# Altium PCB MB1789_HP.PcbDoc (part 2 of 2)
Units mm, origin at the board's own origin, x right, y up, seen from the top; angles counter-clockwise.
Board outline 60 x 34 mm, 4 copper layers (Top Layer, Mid-Layer 1, Mid-Layer 2, Bottom Layer), stack 1.07 mm thick; 66 components, 56 nets, 212 pads, 990 vias.
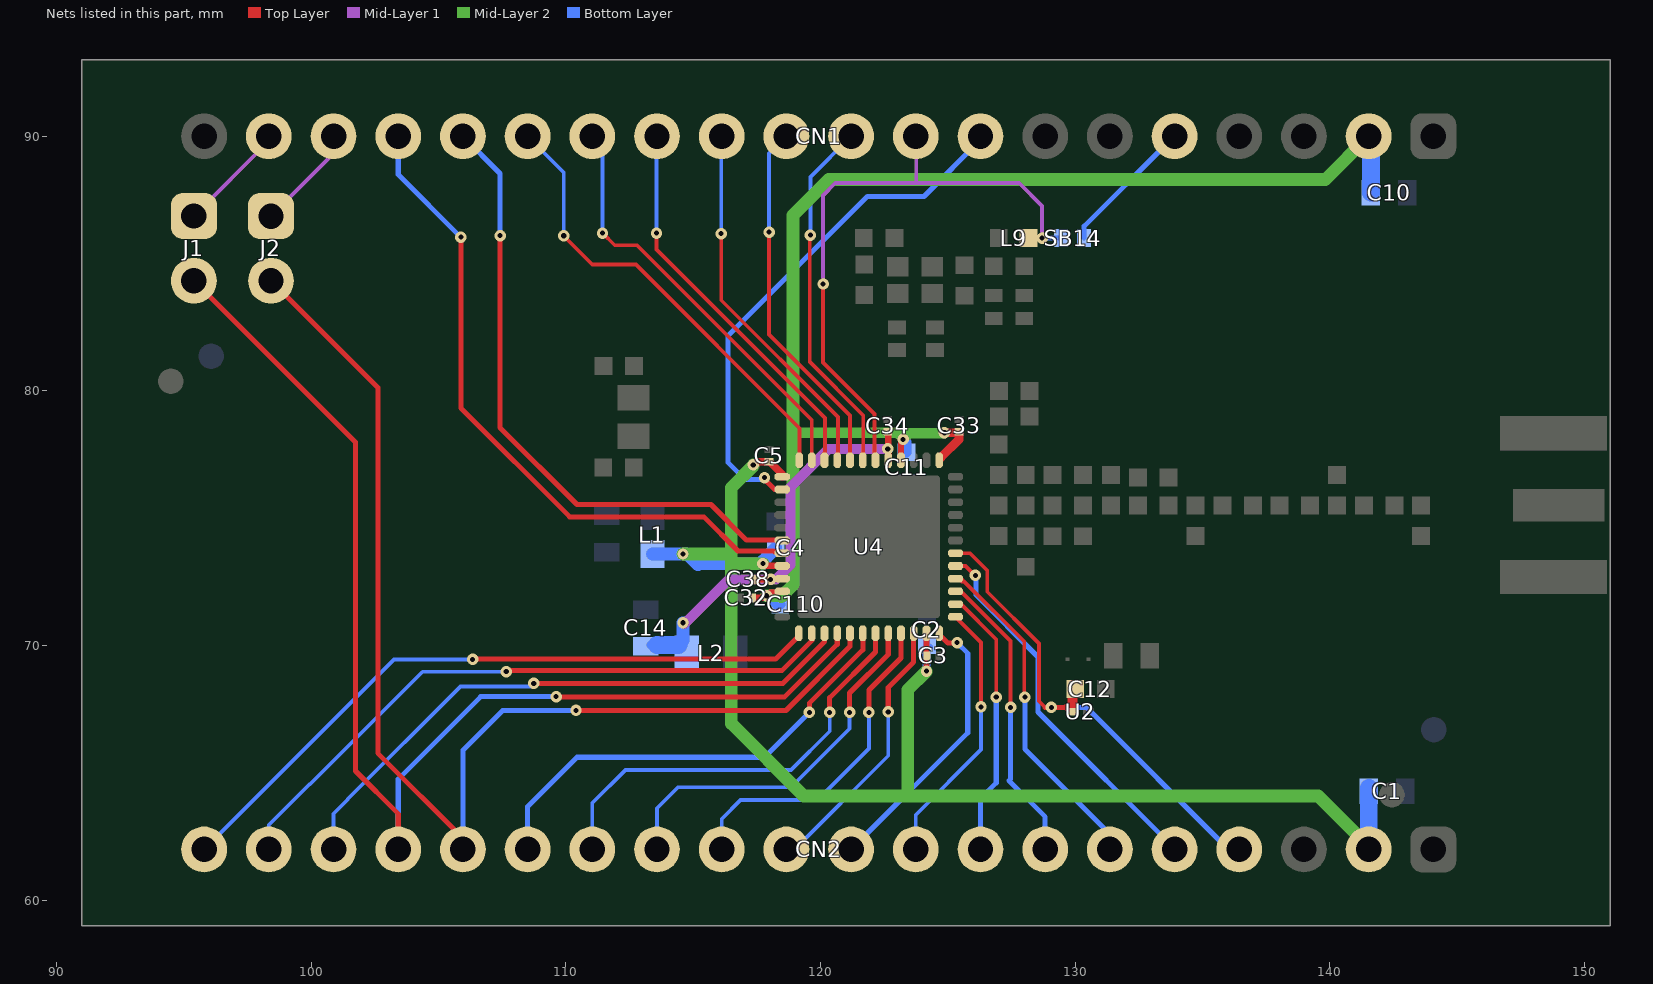
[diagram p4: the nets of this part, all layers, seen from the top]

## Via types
v1: diameter 0.45, hole 0.2, Top Layer to Bottom Layer, 990 vias

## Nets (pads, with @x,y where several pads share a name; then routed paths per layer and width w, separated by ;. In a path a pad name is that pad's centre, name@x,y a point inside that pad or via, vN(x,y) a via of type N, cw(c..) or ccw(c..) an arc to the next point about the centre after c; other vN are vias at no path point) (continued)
NRST: C12.1 CN2.4 U2.1 U4.18 | length 19.4
  Top Layer w0.15: U4.18@125.296,73.632 125.865,73.632 126.545,72.952 126.545,72.121 128.58,70.085 128.58,67.82 128.82,67.58
  Top Layer w0.2: 128.82,67.58 v1(129.06,67.58) 129.588,67.58 129.608,67.6 129.648,67.56 129.688,67.6 U2.1@129.788,67.5 ; C12.1@129.888,68.188 C12.1@130,68.3
  Top Layer w0.4: U2.1@129.888,67.5 C12.1@129.888,68.188
  Bottom Layer w0.2: v1(129.06,67.58) 130.44,67.58 136.02,62 CN2.4@136.44,62
PA0: CN2.14 U4.7 | length 16.9
  Top Layer w0.2: v1(120.36,67.38) 120.36,67.957 122.158,69.755 U4.7@122.158,70.485
  Bottom Layer w0.15: CN2.14@111.04,62 111.04,63.82 112.34,65.12 118.84,65.12 120.36,66.64 v1(120.36,67.38)
PA1: CN2.13 U4.8 | length 14.8
  Top Layer w0.2: v1(121.14,67.38) 121.14,68.14 122.658,69.658 U4.8@122.658,70.485
  Bottom Layer w0.15: CN2.13@113.58,62 113.58,63.62 114.4,64.44 118.84,64.44 121.14,66.74 v1(121.14,67.38)
PA2: CN2.12 U4.9 | length 13.2
  Top Layer w0.2: v1(121.9,67.38) 121.9,68.26 123.158,69.518 U4.9@123.158,70.485
  Bottom Layer w0.15: CN2.12@116.12,62 116.12,63.2 116.86,63.94 119.88,63.94 121.9,65.96 v1(121.9,67.38)
PA3: CN2.11 U4.10 | length 10.8
  Top Layer w0.2: v1@122.6,67.36 122.66,67.42 122.66,68.36 123.658,69.358 U4.10@123.658,70.485
  Bottom Layer w0.15: CN2.11@118.66,62 118.98,62 122.66,65.68 v1(122.66,67.4)
PA4: CN2.10 U4.12 | length 11.1
  Top Layer w0.2: U4.12@124.658,70.485 124.658,70.442 125,70.1 v1@125.4,70.1
  Bottom Layer w0.2: CN2.10@121.2,62 125.78,66.58 125.78,69.7 v1(125.36,70.12)
PA5: CN2.9 U4.13 | length 10.6
  Top Layer w0.15: U4.13@125.296,71.132 126.3,70.128 v1(126.3,67.6)
  Bottom Layer w0.15: CN2.9@123.74,62 123.74,63.36 126.3,65.92 v1(126.3,67.6)
PA6: CN2.8 U4.14 | length 10.7
  Top Layer w0.15: U4.14@125.296,71.632 125.51,71.632 126.9,70.242 v1(126.9,67.98)
  Bottom Layer w0.2: CN2.8@126.28,62 126.28,64 126.9,64.62 v1(126.9,67.98)
PA7: CN2.7 U4.15 | length 11.8
  Top Layer w0.15: U4.15@125.296,72.132 125.51,72.132 127.46,70.182 v1(127.46,67.58)
  Bottom Layer w0.2: v1(127.46,67.58) 127.46,64.76 127.4,64.7 128.82,63.28 CN2.7@128.82,62
PA8: CN2.6 U4.16 | length 13.3
  Top Layer w0.15: U4.16@125.296,72.632 125.528,72.632 125.555,72.605 125.555,72.522 125.638,72.522 128,70.16 v1@128,68
  Bottom Layer w0.2: v1(128.02,67.98) 128.02,65.94 131.36,62.6 CN2.6@131.36,62
PA9: CN2.5 U4.17 | length 15.1
  Top Layer w0.15: U4.17@125.296,73.132 125.688,73.132 v1@126.08,72.74 ; v1@126.08,72.74 v1(126.08,72.76)
  Bottom Layer w0.2: v1@125.99,72.76 126.1,72.76 126.1,72 128.54,69.56 128.54,67.4 CN2.5@133.95,61.99
PA10: CN1.12 U4.33 | length 14.9
  Top Layer w0.15: v1@116.1,86.22 v1(116.1,86.18) 116.1,83.56 120.68,78.98 U4.33@120.68,77.26 ; U4.33@120.658,77.282 U4.33@120.658,77.541
  Bottom Layer w0.15: v1(116.1,86.18) 116.1,89.98 CN1.12@116.12,90
PA11: CN1.13 U4.34 | length 15.9
  Top Layer w0.15: v1@113.56,86.26 v1(113.56,86.2) 113.56,85.56 120.18,78.94 U4.34@120.18,77.3 ; U4.34@120.14,77.2 U4.34@120.14,77.54
  Bottom Layer w0.15: v1(113.56,86.2) 113.56,89.98 CN1.13@113.58,90
PA12: CN1.14 U4.35 | length 16.8
  Top Layer w0.15: v1(111.44,86.2) 111.92,85.72 112.8,85.72 119.658,78.862 U4.35@119.658,77.282
  Bottom Layer w0.15: CN1.14@111.04,90 111.44,89.6 v1(111.44,86.2)
PA13: CN1.15 U4.36 | length 18.8
  Top Layer w0.15: v1@109.92,86.08 111.04,84.96 112.76,84.96 119.18,78.54 U4.36@119.18,77.3
  Mid-Layer 1 w0.15: CN1.15@108.5,89.32 CN1.15@108.5,90
  Bottom Layer w0.15: CN1.15@108.5,90 109.92,88.58 v1(109.92,86.095)
PA14: CN1.16 U4.42 | length 24.9
  Top Layer w0.2: v1@107.42,85.92 107.42,78.56 110.44,75.54 115.7,75.54 117.098,74.142 U4.42@118.62,74.142
  Bottom Layer w0.2: CN1.16@105.96,90 107.42,88.54 v1(107.42,86.1)
PA15: CN1.17 U4.43 | length 26.8
  Top Layer w0.2: v1(105.88,86.04) 105.88,79.331 110.151,75.06 115.42,75.06 116.76,73.72 118.16,73.72 118.2,73.68 118.523,73.68 U4.43@118.58,73.622
  Bottom Layer w0.2: CN1.17@103.42,90 103.42,88.5 v1(105.88,86.04)
PB0: CN1.9 L9.2 SB14.1 U4.30 | length 25
  Top Layer w0.15: v1(120.1,84.2) 120.1,84.18 120.16,84.12 120.08,84.04 120.1,84.02 120.1,81.12 122.125,79.095 122.125,77.315 U4.30@122.158,77.282
  Top Layer w0.2: L9.2@128.16,86 v1(128.7,86)
  Mid-Layer 1 w0.15: v1@120.1,84.08 120.1,87.68 120.58,88.16 127.8,88.16 128.7,87.26 v1(128.7,86) ; CN1.9@123.74,89.94 123.76,89.96 123.76,88.16
  Bottom Layer w0.2: v1(128.7,86) SB14.1@129.45,86
PB2: CN1.10 U4.31 | length 14.7
  Top Layer w0.15: v1(119.6,86.12) 119.66,86.12 119.58,86.2 119.58,81.14 121.68,79.04 U4.31@121.68,77.32 ; U4.31@121.658,77.282 U4.31@121.658,77.562
  Bottom Layer w0.15: v1(119.6,86.12) 119.6,88.4 CN1.10@121.2,90
PB3: CN2.20 U4.1 | length 26.9
  Top Layer w0.2: v1@106.36,69.48 118.24,69.48 119.151,70.391 U4.1@119.151,70.485
  Bottom Layer w0.15: CN2.20@95.8,62 103.26,69.46 v1(106.34,69.46)
PB4: CN2.19 U4.2 | length 25.5
  Top Layer w0.2: v1@107.66,69.02 118.48,69.02 119.658,70.198 U4.2@119.658,70.485
  Bottom Layer w0.15: CN2.19@98.34,62 98.34,62.96 99.94,64.56 99.96,64.56 104.38,68.98 v1(107.66,68.98)
PB5: CN2.18 U4.3 | length 23.8
  Top Layer w0.2: v1@108.78,68.52 118.52,68.52 120.158,70.158 U4.3@120.158,70.485
  Bottom Layer w0.15: CN2.18@100.88,62 100.88,63.4 101.44,63.96 101.44,63.98 105.86,68.4 108.62,68.4 v1(108.74,68.52)
PB6: CN2.17 J1.2 U4.4 | length 48.3
  Top Layer w0.2: J1.2@95.4,84.33 101.74,77.99 101.74,65.08 103.42,63.4 CN2.17@103.42,62 ; v1@109.58,67.98 118.58,67.98 120.658,70.058 U4.4@120.658,70.485
  Bottom Layer w0.2: CN2.17@103.42,62 103.42,64.76 106.66,68 v1(109.62,68)
PB7: CN2.16 J2.2 U4.5 | length 46.7
  Top Layer w0.2: J2.2@98.425,84.328 102.62,80.133 102.62,65.78 105.96,62.44 CN2.16@105.96,62 ; v1(110.4,67.46) 118.64,67.46 121.158,69.978 U4.5@121.158,70.485
  Bottom Layer w0.2: CN2.16@105.96,62 105.96,65.9 107.52,67.46 v1(110.4,67.46)
PB8: CN2.15 U4.6 | length 18.7
  Top Layer w0.15: U4.6@121.618,70.445 U4.6@121.658,70.485 U4.6@121.658,70.235
  Top Layer w0.2: v1@119.56,67.34 v1(119.56,67.38) 119.56,67.74 121.66,69.84 U4.6@121.66,70.56
  Bottom Layer w0.2: CN2.15@108.5,62 108.5,63.68 110.44,65.62 117.8,65.62 v1(119.56,67.38)
PB12: CN1.11 U4.32 | length 14.3
  Top Layer w0.15: v1@117.98,86.26 117.98,82.22 121.158,79.042 U4.32@121.158,77.282
  Bottom Layer w0.15: v1(117.98,86.24) 117.98,89.32 CN1.11@118.66,90
PC13: CN1.8 U4.38 | length 21.1
  Top Layer w0.2: v1(117.8,76.6) 117.869,76.6 117.88,76.589 117.811,76.52 117.751,76.58 118.199,76.132 U4.38@118.498,76.132
  Bottom Layer w0.2: v1@117.811,76.52 117.04,76.52 116.36,77.2 116.36,82.161 121.839,87.64 124.06,87.64 CN1.8@126.32,89.9
UART_RX: CN1.18 J2.1 | length 4.1
  Mid-Layer 1 w0.15: J2.1@98.425,86.868 100.88,89.323 CN1.18@100.88,90
UART_TX: CN1.19 J1.1 | length 4.3
  Mid-Layer 1 w0.15: J1.1@95.4,86.87 98.34,89.81 CN1.19@98.34,90
VDD: C1.2 C2.2 C3.2 C4.2 C5.2 CN2.2 L1.1 U4.11 U4.37 U4.44 | length 58.8
  Top Layer w0.25: v1(117.74,73.22) 117.829,73.22 117.913,73.135 118.495,73.135 U4.44@118.498,73.132 ; v1@124.158,69.002 U4.11@124.158,70.485
  Top Layer w0.28: v1@117.32,77.06 117.48,77.22 C5.2@117.98,77.22 118.01,77.22 118.498,76.731 U4.37@118.498,76.632 ; v1@117.38,77.12 v1@117.44,77.12
  Mid-Layer 2 w0.3: 116.5,73.152 116.548,73.2
  Mid-Layer 2 w0.5: v1(114.6,73.6) 116.5,73.6 ; 116.548,73.2 116.573,73.175 116.658,73.26 116.698,73.22 v1(117.74,73.22) ; v1(117.36,77.1) 117.36,77.065 116.5,76.205 116.5,73.152 116.5,66.94 119.34,64.1 123.42,64.1 ; v1@124.15,68.99 123.42,68.26 123.42,64.1 ; CN2.2@141.56,62.08 139.54,64.1 123.42,64.1
  Bottom Layer w0.25: C2.2@124.18,70.02 C2.2@124.258,69.942
  Bottom Layer w0.3: v1(124.16,69) 124.16,69.844 C2.2@124.258,69.942
  Bottom Layer w0.5: L1.1@113.4,73.6 114.76,73.6 115.185,73.175 115.27,73.26 115.31,73.22 v1(117.74,73.22) 117.74,73.327 117.76,73.347 117.88,73.467 117.873,73.473 C4.2@118.24,73.84
  Bottom Layer w0.7: CN2.2@141.52,61.98 C1.2@141.52,64.42
VDD_TCXO_EXT: CN1.5 SB14.2 | length 5.1
  Bottom Layer w0.2: SB14.2@130.35,86 130.35,86.47 CN1.5@133.6,89.72
VDDPA: C10.1 C11.1 C32.2 C33.2 C110.1 CN1.2 U4.25 U4.28 U4.46 | length 53.3
  Top Layer w0.2: v1(117.88,71.96) 117.88,71.98 118.01,72.11 118.548,72.11 U4.46@118.6,72.162
  Top Layer w0.25: C32.2@117.4,71.88 117.8,71.88 v1(117.88,71.96) ; U4.28@123.158,77.282 123.158,78.038 123.22,78.1 v1(123.24,78.1) ; U4.25@124.658,77.282 U4.25@124.658,77.318
  Top Layer w0.35: U4.25@124.73,77.39 125.44,78.1 C33.2@125.44,78.36 ; v1(124.86,78.36) C33.2@125.425,78.36
  Mid-Layer 2 w0.4: 118.92,78.36 123.015,78.36 123.24,78.135 v1(123.24,78.1) 123.48,78.34 v1@124.84,78.34
  Mid-Layer 2 w0.5: v1(117.88,71.96) 118.42,71.96 118.46,71.92 118.92,72.38 ; 118.92,72.44 118.92,86.9 120.32,88.3 139.82,88.3 CN1.2@141.52,90
  Bottom Layer w0.4: v1(117.88,71.96) 117.94,71.96 117.98,71.92 118.28,71.62 C110.1@118.42,71.62 ; v1(123.24,78.1) 123.275,78.1 123.38,77.995 C11.1@123.38,77.598
  Bottom Layer w0.7: CN1.2@141.52,90 141.607,89.912 C10.1@141.607,87.78
VDDRF1V55: C14.1 C34.2 C38.1 L2.1 U4.29 U4.45 | length 17.3
  Top Layer w0.254: C38.1@117.42,72.6 117.44,72.62 117.46,72.6 v1(118.04,72.6) ; U4.29@122.658,77.282 C34.2@122.658,78.38
  Mid-Layer 1 w0.4: v1(114.6,70.9) 114.649,70.851 116.418,72.62 116.438,72.6 v1(118.04,72.6) 118.2,72.6 118.22,72.62 118.24,72.6 118.82,73.18 118.82,76.22 120.326,77.726 v1(122.64,77.726)
  Bottom Layer w0.4: C14.1@113.363,70.026 C14.1@113.574,70.026 ; L2.1@114.423,70.026 L2.1@114.6,70.204 ; L2.1@114.6,70.071 v1(114.6,70.9)
  Bottom Layer w0.5: L2.1@114.6,70.204 v1(114.6,70.9)
  Bottom Layer w0.7: C14.1@113.574,70.026 L2.1@114.423,70.026
pads on no net: CN1.3 CN1.7 CN2.3 Designator1.1 Designator2.1 Designator3.1 Designator4.1 Designator6.1 U4.22
copper on no net: | length 2656.1
  Top Layer w0.025: 179.628,186.047 182.16,188.579 185.208,191.627 188.256,194.675 191.304,197.723 194.352,200.771 197.4,203.819 200.448,206.867 203.496,209.915 206.544,212.963 208.068,214.487 ; 179.628,187.571 180.636,188.579 183.684,191.627 186.732,194.675 189.78,197.723 192.828,200.771 195.876,203.819 198.924,206.867 201.972,209.915 205.02,212.963 208.068,216.011 ; 179.628,189.095 182.16,191.627 185.208,194.675 188.256,197.723 191.304,200.771 194.352,203.819 197.4,206.867 200.448,209.915 203.496,212.963 206.544,216.011 208.068,217.535 ; 179.628,190.619 180.636,191.627 183.684,194.675 186.732,197.723 189.78,200.771 192.828,203.819 195.876,206.867 198.924,209.915 201.972,212.963 205.02,216.011 208.068,219.059 ; 179.628,192.143 182.16,194.675 185.208,197.723 188.256,200.771 191.304,203.819 194.352,206.867 197.4,209.915 200.448,212.963 203.496,216.011 206.544,219.059 ; 179.628,193.667 180.636,194.675 183.684,197.723 186.732,200.771 189.78,203.819 192.828,206.867 195.876,209.915 198.924,212.963 201.972,216.011 205.02,219.059 ; 179.628,195.191 182.16,197.723 185.208,200.771 188.256,203.819 191.304,206.867 194.352,209.915 197.4,212.963 200.448,216.011 203.496,219.059 ; 179.628,196.715 180.636,197.723 183.684,200.771 186.732,203.819 189.78,206.867 192.828,209.915 195.876,212.963 198.924,216.011 201.972,219.059 ; 179.628,198.239 182.16,200.771 185.208,203.819 188.256,206.867 191.304,209.915 194.352,212.963 197.4,216.011 200.448,219.059 ; 179.628,199.763 180.636,200.771 183.684,203.819 186.732,206.867 189.78,209.915 192.828,212.963 195.876,216.011 198.924,219.059 ; 179.628,201.287 182.16,203.819 185.208,206.867 188.256,209.915 191.304,212.963 194.352,216.011 197.4,219.059 ; 179.628,202.811 180.636,203.819 183.684,206.867 186.732,209.915 189.78,212.963 192.828,216.011 195.876,219.059 ; 179.628,204.335 182.16,206.867 185.208,209.915 188.256,212.963 191.304,216.011 194.352,219.059 ; 179.628,205.859 180.636,206.867 183.684,209.915 186.732,212.963 189.78,216.011 192.828,219.059 ; 179.628,207.383 182.16,209.915 185.208,212.963 188.256,216.011 191.304,219.059 ; 179.628,208.907 180.636,209.915 183.684,212.963 186.732,216.011 189.78,219.059 ; 179.628,210.431 182.16,212.963 185.208,216.011 188.256,219.059 ; 179.628,211.955 180.636,212.963 183.684,216.011 186.732,219.059 ; 179.628,213.479 182.16,216.011 185.208,219.059 ; 179.628,215.003 180.636,216.011 183.684,219.059 ; 179.628,216.527 182.16,219.059 ; 179.628,218.051 180.636,219.059 ; 180.636,185.531 183.684,188.579 186.732,191.627 189.78,194.675 192.828,197.723 195.876,200.771 198.924,203.819 201.972,206.867 205.02,209.915 208.068,212.963 ; 182.16,185.531 185.208,188.579 188.256,191.627 191.304,194.675 194.352,197.723 197.4,200.771 200.448,203.819 203.496,206.867 206.544,209.915 208.068,211.439 ; 183.684,185.531 186.732,188.579 189.78,191.627 192.828,194.675 195.876,197.723 198.924,200.771 201.972,203.819 205.02,206.867 208.068,209.915 ; 185.208,185.531 188.256,188.579 191.304,191.627 194.352,194.675 197.4,197.723 200.448,200.771 203.496,203.819 206.544,206.867 208.068,208.391 ; 186.732,185.531 189.78,188.579 192.828,191.627 195.876,194.675 198.924,197.723 201.972,200.771 205.02,203.819 208.068,206.867 ; 188.256,185.531 191.304,188.579 194.352,191.627 197.4,194.675 200.448,197.723 203.496,200.771 206.544,203.819 208.068,205.343 ; 189.78,185.531 192.828,188.579 195.876,191.627 198.924,194.675 201.972,197.723 205.02,200.771 208.068,203.819 ; 191.304,185.531 194.352,188.579 197.4,191.627 200.448,194.675 203.496,197.723 206.544,200.771 208.068,202.295 ; 192.828,185.531 195.876,188.579 198.924,191.627 201.972,194.675 205.02,197.723 208.068,200.771 ; 194.352,185.531 197.4,188.579 200.448,191.627 203.496,194.675 206.544,197.723 208.068,199.247 ; 195.876,185.531 198.924,188.579 201.972,191.627 205.02,194.675 208.068,197.723 ; 197.4,185.531 200.448,188.579 203.496,191.627 206.544,194.675 208.068,196.199 ; 198.924,185.531 201.972,188.579 205.02,191.627 208.068,194.675 ; 200.448,185.531 203.496,188.579 206.544,191.627 208.068,193.151 ; 201.972,185.531 205.02,188.579 208.068,191.627 ; 203.496,185.531 206.544,188.579 208.068,190.103 ; 205.02,185.531 208.068,188.579 ; 206.544,185.531 208.068,187.055
  Top Layer w0.381: 91.512,188.579 101.924,188.579 125.54,188.579 148.647,188.579 165.153,188.579 179.628,188.579 208.068,188.579 ; 91.512,191.627 101.924,191.627 125.54,191.627 148.647,191.627 165.153,191.627 179.628,191.627 208.068,191.627 ; 91.512,194.675 101.924,194.675 125.54,194.675 148.647,194.675 165.153,194.675 179.628,194.675 208.068,194.675 ; 91.512,197.723 101.924,197.723 125.54,197.723 148.647,197.723 165.153,197.723 179.628,197.723 208.068,197.723 ; 91.512,200.771 101.924,200.771 125.54,200.771 148.647,200.771 165.153,200.771 179.628,200.771 208.068,200.771 ; 91.512,203.819 101.924,203.819 125.54,203.819 148.647,203.819 165.153,203.819 179.628,203.819 208.068,203.819 ; 91.512,206.867 101.924,206.867 125.54,206.867 148.647,206.867 165.153,206.867 179.628,206.867 208.068,206.867 ; 91.512,209.915 101.924,209.915 125.54,209.915 148.647,209.915 165.153,209.915 179.628,209.915 208.068,209.915 ; 91.512,212.963 101.924,212.963 125.54,212.963 148.647,212.963 165.153,212.963 179.628,212.963 208.068,212.963 ; 91.512,216.011 101.924,216.011 125.54,216.011 148.647,216.011 165.153,216.011 179.628,216.011 208.068,216.011 ; 91.512,219.059 208.068,219.059 ; 101.924,222.107 101.924,185.531 ; 125.54,222.107 125.54,185.531 ; 148.647,222.107 148.647,185.531 ; 165.153,222.107 165.153,185.531 ; 179.628,222.107 179.628,185.531 ; 101.924,185.531 125.54,185.531 ; 101.924,185.531 91.512,185.531 91.512,222.107 208.068,222.107 208.068,185.531 179.628,185.531 ; 125.54,185.531 148.647,185.531 ; 148.647,185.531 165.153,185.531 ; 165.153,185.531 179.628,185.531

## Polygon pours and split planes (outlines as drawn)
GND on Top Layer "GND_Top" (solid, remove dead copper, pour order 0): 90.94,93.02 90.98,92.98 150.92,92.98 150.92,59.04 150.86,58.98 91.04,58.98 91.04,92.98
GND on Mid-Layer 1 "GND_L02_P002" (solid, remove dead copper, pour order 2): 91.04,92.98 150.96,92.98 150.96,59.08 151,59.04 150.94,58.98 91.04,58.98 91.04,92.98
GND on Mid-Layer 2 "GND_L03_P004" (solid, remove dead copper, pour order 4): 91.04,92.94 150.76,92.94 150.9,92.8 150.9,59.1 91.04,59.1 90.98,59.16 90.98,93
GND on Bottom Layer "GND_L04_P006" (solid, remove dead copper, pour order 6): 90.98,93 151.02,93 150.96,92.94 150.96,59.1 91.1,59.1 90.98,58.98 90.98,93

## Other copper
Top Layer:
  pour cut-out: 136.247,76.032 143.381,76.032 143.381,74.968 136.246,74.968
  region net NetC28_1: 146.214,75.819 147.139,76.155 147.195,76.155 147.195,74.885 147.167,74.885 146.214,75.218
  region net NetC27_2: 125.489,76.28 126.02,76.28 126.689,77 126.689,76.4 126.319,75.98 125.489,75.98
  pour cut-out: 125.6,77.4 127.54,77.4 127.54,71.5 125.6,73.44
  region net GND: 124.7,84.2 126.4,84.2 126.6,84 126.6,83.4 126.1,83.4 126.1,83 125.4,83 124.9,83.5 124.7,83.5
  pour cut-out: 127.4,80.462 127.7,80.462 127.7,77.2 127.4,77.2
  pour cut-out: 111.84,79.2 113.3,79.2 113.3,78.7 111.84,78.7
  pour cut-out: 111.9,77.4 112.3,77.4 112.3,76.6 112.2,76.7 111.9,76.7
  pour cut-out: 111.9,81.54 112.3,81.54 112.3,80.74 112,80.74 111.9,80.84
  pour cut-out: 127.2,85.3 127.7,85.3 127.7,84.6 127.6,84.5 127.2,84.5
  pour cut-out: 127.4,86.4 127.8,86.4 127.8,85.6 127.4,85.6
  pour cut-out: 122.1,86.4 122.6,86.4 122.6,85.5 122.5,85.6 122.1,85.6
  pour cut-out: 130.462,68.762 130.525,68.7 130.9,68.7 130.9,67.9 130.4,67.9
  pour cut-out: 127.424,73.986 127.49,73.92 129.95,73.92 129.95,73.42 128.29,73.42 127.521,73.42 127.424,73.518
  pour cut-out: 132.925,77.132 133.198,77.132 133.196,74.968 132.923,74.968
  pour cut-out: 126.7,75.1 130.7,75.1 130.7,74.7 126.7,74.7
  pour cut-out: 126.7,76.3 129.941,76.3 129.941,75.972 126.705,75.972 126.695,75.961
  pour cut-out: 129.565,77.215 129.838,77.215 129.838,73.838 129.565,73.838
  pour cut-out: 123.4,77.5 123.4,79.6 121.4,81.6 120.96,82.04 120.96,84.8 121.9,84.8 121.9,86.5 128.8,86.5 128.8,84.8 128.8,81.8 128.8,82 128.3,81.4 126.04,81.4 124.6,79.96 124.6,77.8 124.3,77.5
  region net NetC15_1: 125.1,76.7 125.1,77 126.3,78.2 127,78.2 127,77.6 126.4,77.6 125.5,76.7
  pour cut-out: 118.72,77.04 125.04,77.04 124.98,76.98 124.98,70.76 119.02,70.76 118.82,70.76 119.34,71.28 119.34,71.6 119.2,71.74 118.721,71.261
  pour cut-out: 125.16,78.82 125.72,78.82 125.72,78.46 125.7,78.44 125.16,78.44 125.16,78.78 125.18,78.8
  pour cut-out: 122.38,78.8 122.94,78.8 122.94,78.44 122.92,78.42 122.38,78.42 122.38,78.76 122.4,78.78
  pour cut-out: 117.68,77.64 118.24,77.64 118.24,77.28 118.22,77.26 117.68,77.26 117.68,77.6 117.7,77.62
  pour cut-out: 116.94,72.36 116.94,72.92 117.3,72.92 117.32,72.9 117.32,72.36 116.98,72.36 116.96,72.38
  pour cut-out: 116.88,71.54 116.88,72.1 117.24,72.1 117.26,72.08 117.26,71.54 116.92,71.54 116.9,71.56
  pour cut-out: 124.54,69.84 124.54,69.28 124.18,69.28 124.16,69.3 124.16,69.84 124.5,69.84 124.52,69.82
  text "Layer" at 93.29,219.821 h1.52
  text "Name" at 103.702,219.821 h1.52
  text "Material" at 127.318,219.821 h1.52
  text "Thickness" at 150.425,219.821 h1.52
  text "Constant" at 166.931,219.821 h1.52
  text "Board Layer Stack" at 181.406,219.821 h1.52
  text "Top Overlay" at 103.702,216.773 h1.52
  text "Top Solder" at 103.702,213.725 h1.52
  text "Solder Resist" at 127.318,213.725 h1.52
  text "0.79mil" at 150.425,213.725 h1.52
  text "3.7" at 166.931,213.725 h1.52
  text "1" at 93.29,210.677 h1.52
  text "Top Layer" at 103.702,210.677 h1.52
  text "Copper" at 127.318,210.677 h1.52
  text "1.38mil" at 150.425,210.677 h1.52
  text "Dielectric 1" at 103.702,207.629 h1.52
  text "1x106 + 1x2116" at 127.318,207.629 h1.52
  text "6.30mil" at 150.425,207.629 h1.52
  text "3.7" at 166.931,207.629 h1.52
  text "2" at 93.29,204.581 h1.52
  text "Mid-Layer 1" at 103.702,204.581 h1.52
  text "Copper" at 127.318,204.581 h1.52
  text "1.38mil" at 150.425,204.581 h1.52
  text "Dielectric2" at 103.702,201.533 h1.52
  text "FR-4" at 127.318,201.533 h1.52
  text "24.02mil" at 150.425,201.533 h1.52
  text "5" at 166.931,201.533 h1.52
  text "3" at 93.29,198.485 h1.52
  text "Mid-Layer 2" at 103.702,198.485 h1.52
  text "Copper" at 127.318,198.485 h1.52
  text "1.38mil" at 150.425,198.485 h1.52
  text "Dielectric3" at 103.702,195.437 h1.52
  text "1x106 + 1x2116" at 127.318,195.437 h1.52
  text "6.30mil" at 150.425,195.437 h1.52
  text "3.7" at 166.931,195.437 h1.52
  text "4" at 93.29,192.389 h1.52
  text "Bottom Layer" at 103.702,192.389 h1.52
  text "Copper" at 127.318,192.389 h1.52
  text "1.38mil" at 150.425,192.389 h1.52
  text "Bottom Solder" at 103.702,189.341 h1.52
  text "Solder Resist" at 127.318,189.341 h1.52
  text "0.79mil" at 150.425,189.341 h1.52
  text "3.7" at 166.931,189.341 h1.52
  text "Bottom Overlay" at 103.702,186.293 h1.52
Mid-Layer 1:
  pour cut-out: 123.4,77.5 123.4,79.6 121.4,81.6 120.96,82.04 120.96,84.8 121.9,84.8 121.9,86.5 128.8,86.5 128.8,84.8 128.8,81.8 128.8,82 128.3,81.4 126.04,81.4 124.6,79.96 124.6,77.8 124.3,77.5
  region net GND: 123.9,87.2 126.1,87.2 126.1,83 125.4,83 125.4,83.4 123.9,83.4
  pour cut-out: 146.27,76.36 147.17,76.76 147.17,74.26 146.27,74.56
  pour cut-out: 147.16,76.76 150.96,76.76 150.96,74.26 147.16,74.26
  pour cut-out: 146.38,76.4 146.38,74.6 131.14,74.6 131.14,73.8 130.94,73.4 126.84,73.4 125.64,74.6 125.64,76.9 126.34,77.6 134.54,77.6 134.84,77.3 134.84,76.6 135.04,76.4
Mid-Layer 2:
  pour cut-out: 123.4,77.5 123.4,79.6 121.4,81.6 120.96,82.04 120.96,84.8 121.9,84.8 121.9,86.5 128.8,86.5 128.8,84.8 128.8,81.8 128.8,82 128.3,81.4 126.04,81.4 124.6,79.96 124.6,77.8 124.3,77.5
  region net GND: 123.9,87.2 126.1,87.2 126.1,83 125.4,83 125.4,83.4 123.9,83.4
  region net GND: 124,84.2 125.7,84.2 125.7,83.2 125.4,83.5 124,83.5
Bottom Layer:
  pour cut-out: 123.4,77.5 123.4,79.6 121.4,81.6 120.96,82.04 120.96,84.8 121.9,84.8 121.9,86.5 128.8,86.5 128.8,84.8 128.8,81.8 128.8,82 128.3,81.4 126.04,81.4 124.62,79.98 124.62,77.82 124.3,77.5
  pour cut-out: 115.3,70.4 116.1,70.4 116.1,69 115.3,69
  region net GND: 123.9,87.2 126.1,87.2 126.1,83 125.4,83 125.4,83.4 123.9,83.4
  pour cut-out: 122.98,77.38 123.82,77.38 123.82,76.68 123.82,76.56 122.98,76.56
  pour cut-out: 123.66,70.88 124.709,70.88 124.72,70.891 124.72,70.34 123.64,70.34 123.614,70.366 123.614,70.9
  pour cut-out: 118.6,75.3 119.08,75.3 119.08,73.38 118.62,73.38 118.62,75.26 118.6,75.28
  pour cut-out: 118.78,72.04 118.8,72.06 119.26,72.06 119.26,71.16 119.24,71.14 118.78,71.14

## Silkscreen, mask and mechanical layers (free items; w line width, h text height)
Top Overlay:
  rectangle: 93.48,68.3 100.9,75.4
  lines w0.15: 94.902,91.984 96.209,91.984 ; 95.055,92.322 96.055,92.322 ; 95.305,92.66 95.805,92.66 ; 95.551,90.972 95.551,91.982 ; 130.706,92.029 132.013,92.029 ; 130.86,92.367 131.86,92.367 ; 131.11,92.704 131.61,92.704 ; 131.355,91.016 131.355,92.027 ; 135.784,92.035 137.091,92.035 ; 135.938,92.373 136.938,92.373 ; 136.188,92.711 136.688,92.711 ; 136.433,91.023 136.433,92.033 ; 143.416,92.046 144.722,92.046 ; 143.429,64.028 144.736,64.028 ; 143.569,92.384 144.569,92.384 ; 143.583,64.366 144.583,64.366 ; 143.819,92.722 144.319,92.722 ; 143.833,64.703 144.333,64.703 ; 144.064,91.034 144.064,92.044 ; 144.078,63.015 144.078,64.026
  text "U_TX" at 96.98,91.282 h1
  text "U_RX" at 99.56,91.282 h1
  text "VDDRF" at 140.061,91.133 h1
  text "PA15" at 102.158,91.115 h1
  text "PA14" at 104.847,91.115 h1
  text "PA13" at 107.529,91.114 h1
  text "PA12" at 110.213,91.115 h1
  text "PA11" at 112.891,91.115 h1
  text "PA10" at 115.451,91.115 h1
  text "PB12" at 118.133,91.115 h1
  text "PB2" at 120.811,91.115 h1
  text "PB0" at 122.992,91.115 h1
  text "PC13" at 125.176,91.105 h1
  text "N/C" at 128.1,91.105 h1
  text "PB0" at 133.22,91.105 h1
  text "N/C" at 138.26,91.105 h1
  text "UART_TX" at 92.6,88.3 h1.5 r270
  text "UART_RX" at 100.5,88.1 h1.5 r270
  text "MB1789" at 93.88,77.72 h2
  text "HP Mode - 4L" at 93.78,76.1 h1.23
  text "PB3" at 94.8,60.225 h1
  text "PB4" at 97.359,60.228 h1
  text "PB5" at 99.916,60.228 h1
  text "PB6" at 102.48,60.226 h1
  text "PB7" at 105.039,60.228 h1
  text "PB8" at 107.598,60.226 h1
  text "PA0" at 110.159,60.226 h1
  text "PA1" at 112.716,60.226 h1
  text "PA2" at 115.151,60.226 h1
  text "PA3" at 117.704,60.225 h1
  text "PA4" at 120.263,60.228 h1
  text "PA5" at 122.82,60.228 h1
  text "PA6" at 125.384,60.226 h1
  text "PA7" at 127.943,60.228 h1
  text "PA8" at 130.502,60.226 h1
  text "PA9" at 133.063,60.226 h1
  text "NRST" at 135.13,60.217 h1
  text "N/C" at 138.26,60.216 h1
  text "VDD" at 140.583,60.228 h1
Top Paste:
  lines w0.5: 104.34,85.52 cw(c106.19,85.52) 106.19,87.37 ; 104.349,67.953 104.349,85.453 ; 104.36,68.02 ccw(c106.21,68.02) 106.21,66.17 ; 106.18,66.14 143.08,66.14 ; 106.18,87.38 143.08,87.38 ; 143.09,87.39 cw(c143.09,85.54) 144.94,85.54 ; 143.13,66.15 ccw(c143.13,68) 144.98,68 ; 144.94,78.74 144.94,85.49 ; 144.96,68.02 144.96,72.56
Top Solder:
  rectangle: 128.74,72.72 129.48,73.44
  rectangle: 127.66,77.48 128.4,78.2
  lines w1.5: 144.9,79.6 144.924,79.576 144.924,85.306 ; 144.92,79.46 145.98,78.4 149.2,78.4 ; 144.947,67.964 144.947,71.847 145.7,72.6 149.18,72.6 ; 144.949,68.013 cw(c143.099,68.013) 143.099,66.163 106.199,66.163 cw(c106.199,68.013) 104.349,68.013 104.349,85.513 cw(c106.199,85.513) 106.199,87.363 143.099,87.363 cw(c143.099,85.513) 144.949,85.513
Bottom Solder:
  region: 111.3,72.1 117.52,72.1 117.54,72.12 117.68,71.98 117.68,67.5 111.42,67.5 111.34,67.42 111.34,72.06
Mechanical 1:
  the board outline again, w0.3
Top Assembly (Mech14):
  lines w0.1: 91.043,59.046 91.043,92.947 150.947,92.947 150.947,59.046 91.043,59.046 ; 91.044,59.047 150.948,59.047 150.948,92.948 91.044,92.948 91.044,59.047
Bottom Assembly (Mech15):
  lines w0.1: 91.044,59.047 91.044,92.948 150.948,92.948 150.948,59.047 91.044,59.047
Drill Drawing:
  lines w0.254: 92.847,172.505 94.541,172.505 94.541,174.199 92.847,174.199 92.847,172.505 ; 92.847,178.009 94.541,178.009 93.694,176.315 92.847,178.009
  lines w0.381: 91.328,171.362 292.34,171.362 ; 91.328,178.982 292.34,178.982 ; 105.321,167.552 105.321,182.792 ; 121.826,167.552 121.826,182.792 ; 149.504,167.552 149.504,182.792 ; 162.353,167.552 162.353,182.792 ; 180.992,167.552 180.992,182.792 ; 219.081,167.552 219.081,182.792 ; 234.063,167.552 234.063,182.792 ; 253.006,167.552 253.006,182.792 ; 269.512,167.552 269.512,182.792 ; 91.328,167.552 292.34,167.552 292.34,182.792 91.328,182.792 91.328,167.552
  text "Symbol" at 93.614,180.125 h1.83
  text "Count" at 106.464,180.125 h1.83
  text "Hole Size" at 122.969,180.125 h1.83
  text "Plated" at 150.647,180.125 h1.83
  text "Hole Type" at 163.496,180.125 h1.83
  text "Drill Layer Pair" at 182.135,180.125 h1.83
  text "Via/Pad" at 220.224,180.125 h1.83
  text "Pad Shape" at 235.206,180.125 h1.83
  text "Template" at 254.149,180.125 h1.83
  text "Description" at 270.655,180.125 h1.83
  text "990" at 106.464,176.315 h1.52
  text "0.200mm (7.87mil)" at 122.969,176.315 h1.52
  text "PTH" at 150.647,176.315 h1.52
  text "Round" at 163.496,176.315 h1.52
  text "Top Layer - Bottom Layer" at 182.135,176.315 h1.52
  text "Via" at 220.224,176.315 h1.52
  text "Rounded" at 235.206,176.315 h1.52
  text "v45h20" at 254.149,176.315 h1.52
  text "44" at 106.464,172.505 h1.52
  text "1.000mm (39.37mil)" at 122.969,172.505 h1.52
  text "PTH" at 150.647,172.505 h1.52
  text "Round" at 163.496,172.505 h1.52
  text "Top Layer - Bottom Layer" at 182.135,172.505 h1.52
  text "Pad" at 220.224,172.505 h1.52
  text "(Mixed)" at 235.206,172.505 h1.52
  text "(Mixed)" at 254.149,172.505 h1.52
  text "1034 Total" at 106.464,168.695 h1.52
  text "mils" at 115.217,153.09 h2.54
  text "mils" at 126.271,153.09 h2.54

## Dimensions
151.002,59.018 to 90.991,58.863 on Bottom Assembly
90.936,93.075 to 90.956,59.033 on Bottom Assembly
